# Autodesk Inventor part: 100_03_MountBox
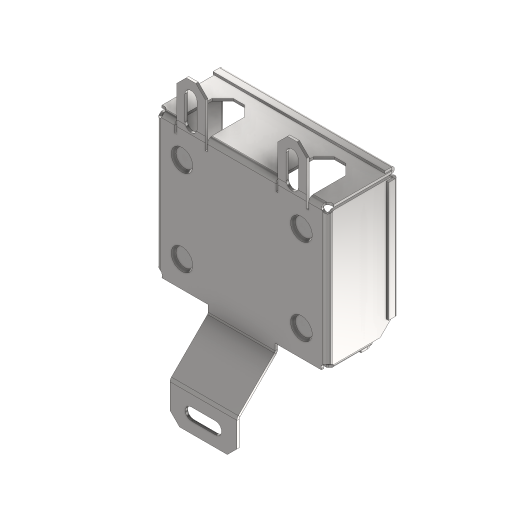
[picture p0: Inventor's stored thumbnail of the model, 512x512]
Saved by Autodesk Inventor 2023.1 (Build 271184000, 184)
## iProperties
Company: Fabian Stasiak CAD Consulting
Category: Autodesk® Inventor® Tutorial Series
Created: 2005-11
Part Number: 100_03_MountBox
Material: Steel
Document SubType Name: Sheet Metal
Designer: F.Stasiak
Density: 1 g/cm^3
Sheet Metal Rule: Steel 2.5 mm/Round
Sheet Metal Width: 328,562 mm
Sheet Metal Length: 332,240 mm
Sheet Metal Area: 109161,518 mm^2
Appearance: Semi-Polished
Description: Mounting Box RX7
Catalog Web Link: www.expertbooks.eu
Flat Pattern Width: 32.8562 cm
Flat Pattern Length: 33.224 cm
Flat Pattern Area: 1091.62 cm^2
FLATAREA: =<FLAT PATTERN AREA>
Thickness: 2,500 mm
Author: F.Stasiak
Subject: Sheet Metal Design. Basic and Advanced techniques
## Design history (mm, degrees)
node "Powierzchnia1"
  sketch "Szkic2"
    geometry: L1 (-75, 90)-(75, 90); L2 (75, 90)-(75, -90); L3 (75, -90)-(-75, -90); L4 (-75, -90)-(-75, 90); L5 (0, 90)-(0, -90); 2 further points
    constraints: 10 end point, 3 midpoint, 2 parallel, 1 coincident, 1 horizontal, 1 perpendicular
    dimensions: "d2" = 150 distance of L2.end L3.end; "d3" = 180 distance of L1.end L2.end
node "Kołnierz6"
feature "Fazowanie narożnika3" dims "d68" = 20, "d69" = 6, angle "d70" = 45 deg
node "Kołnierz7"
feature "Narożnik4" dims "d156" = 10 (= CornerReliefSize), "d157" = 2.5 (= BendRadius), "d158" = 2.5 (= GapSize), "d159" = 0, "d160" = 10, "d223" = 2.5 (= Thickness)
feature "Narożnik5" dims "d161" = 10 (= CornerReliefSize), "d162" = 2.5 (= BendRadius), "d163" = 2.5 (= GapSize), "d164" = 0, "d165" = 10, "d223" = 2.5 (= Thickness)
node "Płaszczyzna konstrukcyjna2"
node "Powierzchnia3"
  sketch "Szkic11"
    geometry: L1 (-231, 119.076)-(-195, 119.076); L2 (-195, 119.076)-(-195, 49.076); L3 (-195, 49.076)-(-231, 49.076); L4 (-231, 49.076)-(-231, 119.076); L5 (-142.5, 44.076)-(-145, 44.076) reference; L6 (-142.5, 124.076)-(-145, 124.076) reference; L7 (-145, 167.518)-(-145, 0.634) reference; 3 further points
    constraints: 8 end point, 2 parallel, 1 horizontal, 1 perpendicular
    dimensions: "d82" = 5 distance between parallel lines of L5 L3; "d83" = 5 distance between parallel lines of L6 L1 (= d82); "d84" = 36 distance of L1.start L1.end; "d85" = 50 distance between parallel lines of L7 L2
feature "Fazowanie narożnika4" dims "d91" = 10, "d92" = 6, angle "d93" = 45 deg
feature "Bend13" [Gięcie] dims "d223" = 2.5 (= Thickness), "d224" = 2.5 (= BendReliefWidth), "d225" = 1.25 (= BendReliefDepth), "d226" = 5 (= MinimumRemnant), "d227" = 2.5 (= TransitionRadius), "d228" = 2.5 (= BendRadius), "SeamGap" = 0.01
node "Unfold1"
sketch "Sketch26"
  geometry: L1 (132.163, 155)-(190.163, 155); L2 (190.163, 155)-(190.163, 121); L3 (190.163, 121)-(132.163, 121); L4 (132.163, 121)-(132.163, 155); L5 (0, 175)-(138.153, 175) reference; L6 (210.163, 175)-(210.163, -5) reference; L7 (132.163, 153)-(188.163, 153); L8 (188.163, 153)-(188.163, 123); L9 (188.163, 123)-(132.163, 123); 3 further points
  constraints: 14 end point, 3 perpendicular, 2 horizontal, 2 midpoint, 2 parallel, 2 point on line, 1 horizontal alignment
  dimensions: "d229" = 58 distance of L2.end L3.end; "d230" = 34 distance of L1.end L2.end; "d231" = 20 distance between parallel lines of L1 L5; "d232" = 20 distance between parallel lines of L6 L2; "d233" = 30 distance between parallel lines of L9 L7; "d234" = 56 distance of L7.start L7.end
cut "Cut3" sketch "Sketch26" dims "d235" = 2.5 (= Thickness), "d236" = 0
feature "Corner Chamfer9" [Fazowanie narożnika] dims "d237" = 10, "d238" = 6, angle "d239" = 45 deg
feature "Corner Chamfer10" [Fazowanie narożnika] dims "d240" = 11, "d241" = 6, angle "d242" = 45 deg
mirror "Mirror3"
node "Refold1"
feature "Hem11" dims "d223" = 2.5 (= Thickness), "d243" = 2.5 (= BendReliefWidth), "d244" = 1.25 (= BendReliefDepth), "d245" = 5 (= MinimumRemnant), "d246" = 2.5 (= TransitionRadius), "d247" = 10 (= 4 x Thickness), "d248" = 1.25 (= 0.5 x Thickness), "d249" = 0.625 (= 0.5 x d248), "SeamGap" = 0.01
feature "Hem12" dims "d223" = 2.5 (= Thickness), "d250" = 2.5 (= BendReliefWidth), "d251" = 1.25 (= BendReliefDepth), "d252" = 5 (= MinimumRemnant), "d253" = 2.5 (= TransitionRadius), "d254" = 10 (= 4 x Thickness), "d255" = 1.25 (= 0.5 x Thickness), "d256" = 0.625 (= 0.5 x d255), "SeamGap" = 0.01
feature "Hem13" dims "d223" = 2.5 (= Thickness), "d257" = 2.5 (= BendReliefWidth), "d258" = 1.25 (= BendReliefDepth), "d259" = 5 (= MinimumRemnant), "d260" = 2.5 (= TransitionRadius), "d261" = 10 (= 4 x Thickness), "d262" = 1.25 (= 0.5 x Thickness), "d263" = 0.625 (= 0.5 x d262), "SeamGap" = 0.01
feature "Hem14" dims "d223" = 2.5 (= Thickness), "d264" = 2.5 (= BendReliefWidth), "d265" = 1.25 (= BendReliefDepth), "d266" = 5 (= MinimumRemnant), "d267" = 2.5 (= TransitionRadius), "d268" = 10 (= 4 x Thickness), "d269" = 1.25 (= 0.5 x Thickness), "d270" = 0.625 (= 0.5 x d269), "SeamGap" = 0.01
feature "Hem15" dims "d223" = 2.5 (= Thickness), "d271" = 2.5 (= BendReliefWidth), "d272" = 1.25 (= BendReliefDepth), "d273" = 5 (= MinimumRemnant), "d274" = 2.5 (= TransitionRadius), "d275" = 10 (= 4 x Thickness), "d276" = 1.25 (= 0.5 x Thickness), "d277" = 0.625 (= 0.5 x d276), "SeamGap" = 0.01
sketch "Sketch32"
  geometry: L1 (132.163, 155)-(132.163, 153) reference; L2 (139.076, 123)-(132.163, 123) reference; L3 (132.163, 153)-(132.163, 123); L4 (132.163, 138)-(188.163, 138); L5 (188.163, 133)-(188.163, 143) reference; L6 (132.163, 49)-(132.163, 47) reference; L7 (132.163, 17)-(132.163, 15) reference; L8 (132.163, 47)-(132.163, 17); L9 (132.163, 32)-(188.163, 32); L10 (188.163, 37)-(188.163, 27) reference; 3 further points
  constraints: 8 end point, 6 midpoint, 2 vertical
feature "iFeature18:1" sketch "Sketch32"
sketch "Sketch33"
  geometry: L1 (-195, 119.076)-(-195, 49.076) reference; L2 (-195, 84.076)-(-231, 84.076); L3 (-231, 59.076)-(-231, 109.076) reference; 2 further points
  constraints: 3 midpoint, 2 end point
feature "iFeature18:2" sketch "Sketch33"
sketch "Sketch34"
  geometry: L1 (26.576, 22.5)-(116.576, 22.5); L2 (116.576, 22.5)-(116.576, 147.5); L3 (116.576, 147.5)-(26.576, 147.5); L4 (26.576, 147.5)-(26.576, 22.5); L5 (-3.424, 175)-(-3.424, -5) reference; L6 (-0.924, -2.5)-(124.076, -2.5) reference; L7 (124.076, 172.5)-(-0.924, 172.5) reference; L8 (141.576, 0)-(141.576, 45) reference; 1 further point
  constraints: 8 end point, 2 parallel, 1 horizontal, 1 perpendicular
  dimensions: "d284" = 30 distance between parallel lines of L5 L4; "d285" = 25 distance between parallel lines of L6 L1; "d286" = 25 distance between parallel lines of L7 L3; "d287" = 25 distance between parallel lines of L8 L2
feature "iFeature5:1" sketch "Sketch34"
node "A-Side Definition"
feature "؏耀؎耀؋耀؊耀؉耀؄耀؃耀׽耀" dims "d2" = 150, "d3" = 180, "d4" = 2.5 (= BendRadius), "d56" = 2.5 (= BendReliefWidth), "d57" = 1.25 (= BendReliefDepth), "d58" = 5 (= MinimumRemnant), "d59" = 2.5 (= BendRadius), "d60" = 70 (= WW), "d61" = 90 deg, "d62" = 2.5 (= BendRadius), "d63" = 10 (= CornerReliefSize), "d64" = 2.5 (= GapSize), "d65" = 2.5 (= JacobiRadiusSize), "d66" = 10, "d67" = 10, "d68" = 20, "d69" = 6, "d70" = 45 deg, "d71" = 2.5 (= BendReliefWidth), "d72" = 1.25 (= BendReliefDepth), "d73" = 5 (= MinimumRemnant), "d74" = 2.5 (= BendRadius), "d75" = 50, "d76" = 90 deg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
feature "ٲ耀ٱ耀ٮ耀٭耀٬耀٧耀٦耀٠耀" dims "d2" = 150, "d3" = 180, "d4" = 2.5 (= BendRadius), "d56" = 2.5 (= BendReliefWidth), "d57" = 1.25 (= BendReliefDepth), "d58" = 5 (= MinimumRemnant), "d59" = 2.5 (= BendRadius), "d60" = 70 (= WW), "d61" = 90 deg, "d62" = 2.5 (= BendRadius), "d63" = 10 (= CornerReliefSize), "d64" = 2.5 (= GapSize), "d65" = 2.5 (= JacobiRadiusSize), "d66" = 10, "d67" = 10, "d68" = 20, "d69" = 6, "d70" = 45 deg, "d71" = 2.5 (= BendReliefWidth), "d72" = 1.25 (= BendReliefDepth), "d73" = 5 (= MinimumRemnant), "d74" = 2.5 (= BendRadius), "d75" = 50, "d76" = 90 deg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
node "Bryła1"
node "Korpusy bryłowe"
node "Korpusy powierzchniowe"
feature "Płyta1" dims "d223" = 2.5 (= Thickness)
sketch "Szkic9"
  geometry: L1 (0, 70)-(-150, 70); L2 (-150, 70)-(-150, 0); 1 other entity
  constraints: 4 end point, 4 other
feature "Płyta8" dims "d56" = 2.5 (= BendReliefWidth), "d57" = 1.25 (= BendReliefDepth), "d58" = 5 (= MinimumRemnant), "d59" = 2.5 (= BendRadius), "d60" = 70 (= WW), "d61" = 90 deg, "d62" = 2.5 (= BendRadius), "d63" = 10 (= CornerReliefSize), "d64" = 2.5 (= GapSize), "d65" = 2.5 (= JacobiRadiusSize), "d66" = 10, "d67" = 10, "d223" = 2.5 (= Thickness), "SeamGap" = 0.01
feature "Gięcie7" dims "d56" = 2.5 (= BendReliefWidth), "d57" = 1.25 (= BendReliefDepth), "d58" = 5 (= MinimumRemnant), "d59" = 2.5 (= BendRadius), "d60" = 70 (= WW), "d61" = 90 deg, "d62" = 2.5 (= BendRadius), "d223" = 2.5 (= Thickness), "SeamGap" = 0.01
feature "Narożnik1" dims "d60" = 70 (= WW), "d61" = 90 deg, "d63" = 10 (= CornerReliefSize), "d64" = 2.5 (= GapSize), "d65" = 2.5 (= JacobiRadiusSize)
sketch "Szkic10"
  geometry: L1 (50, 0)-(50, 45); L2 (50, 45)-(0, 45); 1 other entity
  constraints: 4 end point, 4 other
feature "Płyta9" dims "d71" = 2.5 (= BendReliefWidth), "d72" = 1.25 (= BendReliefDepth), "d73" = 5 (= MinimumRemnant), "d74" = 2.5 (= BendRadius), "d75" = 50, "d76" = 90 deg, "d77" = 2.5 (= BendRadius), "d78" = 10 (= CornerReliefSize), "d79" = 2.5 (= GapSize), "d80" = 2.5 (= JacobiRadiusSize), "d223" = 2.5 (= Thickness), "SeamGap" = 0.01
feature "Gięcie8" dims "d71" = 2.5 (= BendReliefWidth), "d72" = 1.25 (= BendReliefDepth), "d73" = 5 (= MinimumRemnant), "d74" = 2.5 (= BendRadius), "d75" = 50, "d76" = 90 deg, "d77" = 2.5 (= BendRadius), "d223" = 2.5 (= Thickness), "SeamGap" = 0.01
feature "Narożnik2" dims "d75" = 50, "d76" = 90 deg, "d78" = 10 (= CornerReliefSize), "d79" = 2.5 (= GapSize), "d80" = 2.5 (= JacobiRadiusSize)
feature "Płyta10" dims "d86" = 2.5 (= BendRadius), "d87" = 2.5 (= BendReliefWidth), "d89" = 5 (= MinimumRemnant), "d223" = 2.5 (= Thickness)
feature "Gięcie9" dims "d86" = 2.5 (= BendRadius), "d87" = 2.5 (= BendReliefWidth), "d88" = 1.25 (= BendReliefDepth), "d89" = 5 (= MinimumRemnant), "d90" = 2.5 (= BendRadius), "d223" = 2.5 (= Thickness), "SeamGap" = 0.01
sketch "Sketch27"
  geometry: L1 (2.5, 0)-(0, 0); L2 (-1.25, 0)-(-1.25, -6.875); L3 (-1.25, -6.875)-(-3.75, -6.875); L4 (-3.75, -6.875)-(-3.75, 0); A1 r 0.625 centre (-0.625, 0) between (0, 0) and (-1.25, 0); A2 r 3.125 centre (-0.625, 0) between (2.5, 0) and (-3.75, 0)
  constraints: 8 end point, 4 point on circle
sketch "Sketch28"
  geometry: L1 (2.5, 0)-(0, 0); L2 (-1.25, 0)-(-1.25, -6.875); L3 (-1.25, -6.875)-(-3.75, -6.875); L4 (-3.75, -6.875)-(-3.75, 0); A1 r 0.625 centre (-0.625, 0) between (0, 0) and (-1.25, 0); A2 r 3.125 centre (-0.625, 0) between (2.5, 0) and (-3.75, 0)
  constraints: 8 end point, 4 point on circle
sketch "Sketch29"
  geometry: L1 (2.5, 0)-(0, 0); L2 (-1.25, 0)-(-1.25, -6.875); L3 (-1.25, -6.875)-(-3.75, -6.875); L4 (-3.75, -6.875)-(-3.75, 0); A1 r 0.625 centre (-0.625, 0) between (0, 0) and (-1.25, 0); A2 r 3.125 centre (-0.625, 0) between (2.5, 0) and (-3.75, 0)
  constraints: 8 end point, 4 point on circle
sketch "Sketch30"
  geometry: L1 (2.5, 0)-(0, 0); L2 (-1.25, 0)-(-1.25, -6.875); L3 (-1.25, -6.875)-(-3.75, -6.875); L4 (-3.75, -6.875)-(-3.75, 0); A1 r 0.625 centre (-0.625, 0) between (0, 0) and (-1.25, 0); A2 r 3.125 centre (-0.625, 0) between (2.5, 0) and (-3.75, 0)
  constraints: 8 end point, 4 point on circle
sketch "Sketch31"
  geometry: L1 (2.5, 0)-(0, 0); L2 (-1.25, 0)-(-1.25, -6.875); L3 (-1.25, -6.875)-(-3.75, -6.875); L4 (-3.75, -6.875)-(-3.75, 0); A1 r 0.625 centre (-0.625, 0) between (0, 0) and (-1.25, 0); A2 r 3.125 centre (-0.625, 0) between (2.5, 0) and (-3.75, 0)
  constraints: 8 end point, 4 point on circle
feature "Definition1"
